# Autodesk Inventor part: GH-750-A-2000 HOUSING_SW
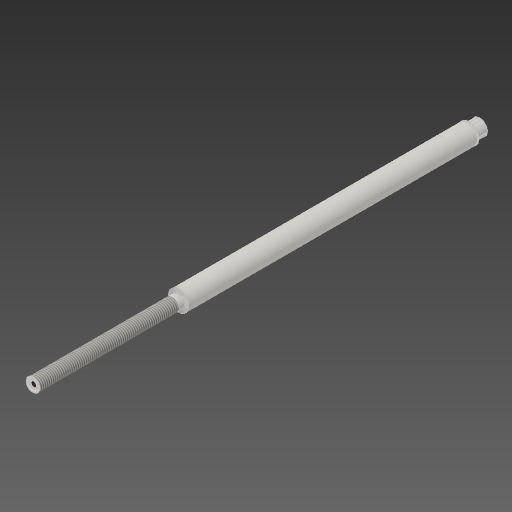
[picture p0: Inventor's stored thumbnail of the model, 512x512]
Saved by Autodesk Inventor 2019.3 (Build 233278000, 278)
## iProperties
Created: 2018-11
Part Number: GH-750-A-2000 HOUSING_SW
Material: Generic
Document SubType Name: Modeling
Designer: Justin
Density: 1 g/cm^3
Appearance: Default
Author: Justin
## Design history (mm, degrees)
node "Assembly1"
body "Solid1"
node "Part1:1"
node "Part2:1"
body "Solid2"
node "Part3:1"
body "Solid3"
node "Part4:1"
body "Solid4"
node "Part5:1"
body "Solid5"
